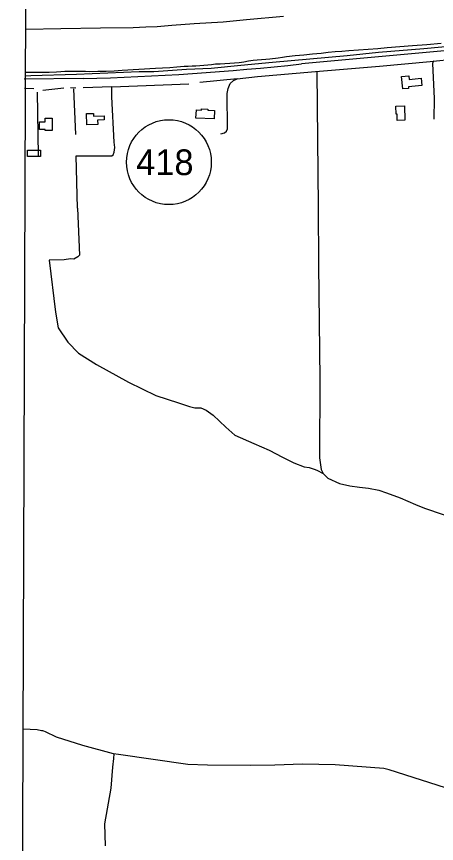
# Model space of a CAD drawing. Extents: x 3146026 to 3183936, y 897894 to 923344.
# Drawn here: x 3150246 to 3151879, y 910091 to 913306 of the extents above; entities that cross this region are included whole.
import ezdxf

# ---------------------------------------------------------------- set-up
doc = ezdxf.new("R2010")
doc.units = 0
for name, color, linetype in [('V-BLDG-OTLN', 7, 'Continuous'), ('V-GRID-FRAM', 7, 'Continuous'), ('V-LEVE-TOET', 7, 'Continuous'), ('V-ROAD-CNTR', 7, 'Continuous'), ('V-ROAD-IDEN', 7, 'Continuous'), ('V-TOPO-SHOR', 7, 'Continuous')]:
    doc.layers.add(name, color=color, linetype=linetype)

msp = doc.modelspace()

# ---------------------------------------------------------------- linework, layer by layer
at = {"layer": 'V-BLDG-OTLN'}
for points in [[(3151819.8, 913066), (3151822.6, 913037.5), (3151770.6, 913032.5), (3151771.2, 913026.5), (3151748.2, 913024.2), (3151743.5, 913072.5), (3151772.3, 913075.2), (3151773.6, 913061.5)], [(3151014.2, 912907.6), (3150943.7, 912911.2), (3150945.3, 912943), (3150965.4, 912942), (3150965.6, 912947.3), (3150990.5, 912946), (3150990.2, 912941.7), (3151015.9, 912940.4)], [(3151754.5, 912958.9), (3151756.3, 912903.2), (3151726.6, 912902.2), (3151725.9, 912926.1), (3151722.9, 912926), (3151721.8, 912957.9)], [(3150384.9, 912911.2), (3150385, 912862.5), (3150357.3, 912862.4), (3150357.3, 912866.7), (3150335.4, 912866.7), (3150335.4, 912896.7), (3150357.4, 912896.7), (3150357.4, 912911.1)], [(3150586.7, 912919.8), (3150587.1, 912903.7), (3150561.4, 912903), (3150561.8, 912886.3), (3150519.5, 912885.2), (3150518.3, 912928.8), (3150544.6, 912929.4), (3150544.8, 912918.7)], [(3150339.3, 912786.6), (3150339.2, 912762.1), (3150288.7, 912762.3), (3150288.8, 912786.8)]]:
    msp.add_lwpolyline(points, close=True, dxfattribs=at)
at = {"layer": 'V-GRID-FRAM'}
msp.add_lwpolyline([(3150311.9, 921563.1), (3181637, 921462.9), (3181586.7, 903274.3), (3150245.8, 903374.5), (3150311.9, 921563.1)], dxfattribs=at)
at = {"layer": 'V-LEVE-TOET'}
for points in [[(3150281.7, 913256.7), (3150418.2, 913258.6), (3150572.4, 913261.4), (3150699.2, 913263.7), (3150748.3, 913265.1), (3150792.4, 913266.8), (3150850.4, 913271.8), (3150936.8, 913278.2), (3151049.1, 913284.7), (3151140.2, 913293.8), (3151284.7, 913307.1)], [(3151897.2, 913200.9), (3151841.5, 913196.2), (3151785.8, 913192), (3151737, 913188.1), (3151688.2, 913184.1), (3151650.9, 913180.7), (3151613.4, 913177.5), (3151576, 913174.5), (3151538.6, 913171.8), (3151511.6, 913170.1), (3151484.8, 913168), (3151457.9, 913165.5), (3151431.1, 913162.6), (3151397.3, 913159.3), (3151363.6, 913156), (3151329.8, 913152.6), (3151296.1, 913149), (3151279.9, 913146.6), (3151263.7, 913144.4), (3151231.3, 913140.6), (3151215, 913139), (3151198.7, 913137.6), (3151182.4, 913136.4), (3151166.1, 913135.4), (3151148, 913131.9), (3151129.9, 913128.9), (3151111.7, 913126.4), (3151093.4, 913124.3), (3151075.1, 913122.6), (3151056.7, 913121.4), (3151038.4, 913120.6), (3151020, 913120.3), (3151004.8, 913118.2), (3150989.6, 913116.5), (3150974.4, 913115), (3150959.1, 913113.8), (3150943.8, 913112.8), (3150928.5, 913112.2), (3150913.2, 913111.8), (3150897.9, 913111.7), (3150869.9, 913108.7), (3150841.9, 913106.4), (3150813.9, 913104.7), (3150785.8, 913103.6), (3150721.6, 913099.9), (3150657.3, 913096.1), (3150625.7, 913094), (3150594, 913092.5), (3150562.3, 913091.7), (3150530.5, 913091.4), (3150514.4, 913091.9), (3150498.3, 913092.3)], [(3150498.3, 913092.3), (3150482.2, 913092.4), (3150466, 913092.3), (3150449.9, 913092), (3150433.8, 913091.5), (3150417.6, 913090.8), (3150401.5, 913089.8), (3150373.1, 913088.7), (3150344.6, 913088), (3150316.1, 913087.6), (3150287.6, 913087.7), (3150281.1, 913087.8)]]:
    msp.add_lwpolyline(points, dxfattribs=at)
at = {"layer": 'V-ROAD-CNTR'}
for points in [[(3152764.7, 913249.6), (3151354, 913121.3)], [(3150504.4, 913064.4), (3150275, 913062.2)]]:
    msp.add_lwpolyline(points, dxfattribs=at)
msp.add_arc((3150227.2, 923566.8), 10506.1, 271.51204, 276.15701, dxfattribs=at)
at = {"layer": 'V-ROAD-IDEN'}
msp.add_circle((3150838.5, 912739.6), 165, dxfattribs=at)
at = {"layer": 'V-TOPO-SHOR'}
for p, q in [((3151854.8, 913131.3), (3152006.9, 913146.9)), ((3150616.2, 913032.5), (3150916.2, 913044.2)), ((3151104.7, 913063.2), (3150958.4, 913048.9)), ((3150313.3, 913025.3), (3150277.1, 913026.2)), ((3150326, 913011.9), (3150329.7, 912765)), ((3150348, 913020), (3150429.5, 913028)), ((3150456.4, 913029.5), (3150476, 913028.2)), ((3150467.9, 913024.8), (3150475.6, 912846.8))]:
    msp.add_line(p, q, dxfattribs=at)
for points in [[(3153574.1, 913209.4), (3153385.3, 913235.5), (3153165.9, 913253.6), (3153079.7, 913260.9), (3152956.4, 913265.6), (3152855.6, 913267.5), (3152817.2, 913269.3), (3152700.8, 913259.3), (3152400.2, 913227.3), (3152126, 913206.2), (3152036.5, 913196.2), (3151984.9, 913193.9), (3151829.9, 913179.9), (3151653.9, 913165.6), (3151531.6, 913152.9), (3151242.1, 913127.1), (3151118.4, 913115.8), (3151003.4, 913104.3), (3150906.8, 913100.4), (3150779.6, 913091.4), (3150722.9, 913091.4), (3150478.8, 913080.4), (3150300.9, 913075.7), (3150277.6, 913073.4)], [(3151408.8, 913091.5), (3151657.6, 913112.5), (3151854.8, 913131.3)], [(3151867.2, 913133.2), (3151864, 913123.1), (3151870.6, 912986.5), (3151869.2, 912907.4)], [(3151040.3, 912849.4), (3151054.9, 912853.3), (3151062.3, 912860.4), (3151066.2, 912869.7), (3151065.5, 913006.2), (3151068.9, 913026.4), (3151076.6, 913045.1), (3151089.3, 913057.1), (3151104.7, 913063.2), (3151182.6, 913072.1), (3151408.8, 913091.5)], [(3151414.6, 913091.4), (3151419.7, 912567.2), (3151421, 912339.3), (3151425.3, 911896.4), (3151424.5, 911590.2), (3151430.5, 911545), (3151438.1, 911529.6), (3151456.5, 911511.7), (3151502.4, 911490.1), (3151542.8, 911481.8), (3151580.4, 911476.5), (3151615.2, 911472.6), (3151654.9, 911465.1), (3151685.1, 911454.1), (3151738.3, 911435.3), (3151797.8, 911408.3), (3151833, 911395.1), (3151977.6, 911345.5), (3152095.1, 911315.6), (3152179.6, 911298.1), (3152225, 911287.5), (3152260.5, 911282.9), (3152300.4, 911284), (3152313.5, 911283.7)], [(3150483.3, 912561.4), (3150477.7, 912764), (3150616.4, 912764), (3150622.3, 912768.2), (3150626.2, 912779), (3150628.8, 912797), (3150625, 912817.5), (3150615.9, 912994.1), (3150616.2, 913032.5), (3150505, 913028.9)], [(3150483.3, 912561.4), (3150490.8, 912377.5), (3150484.8, 912371.9), (3150468.6, 912362.1), (3150455.6, 912363.9), (3150430.8, 912360.2), (3150372.7, 912358.9), (3150397.9, 912156.4), (3150407.9, 912095.2), (3150445.6, 912040.5), (3150486.6, 911997.3), (3150556.6, 911953.4), (3150681, 911884.8), (3150787.1, 911832.7), (3150876.3, 911804.2), (3150918.1, 911790), (3150939.7, 911785.1), (3150962.9, 911784.5), (3150983, 911775.2), (3151010.1, 911755.7), (3151059.6, 911709.4), (3151095.1, 911677.9), (3151168.3, 911645.5), (3151228.6, 911620.7), (3151280.1, 911593.2), (3151324.5, 911570.3), (3151364.8, 911554.7), (3151383.6, 911552.8), (3151403.7, 911546.4), (3151413.8, 911541.8), (3151438.1, 911529.6)], [(3152496.7, 910100.6), (3152308.5, 910167.6), (3152106.8, 910240.1), (3151946.4, 910296.6), (3151695, 910377.9), (3151675.1, 910382.7), (3151484.7, 910396.4), (3151358.1, 910399.1), (3151250.4, 910395.3), (3151155, 910394.4), (3150989.3, 910395.4), (3150911.6, 910398.3), (3150642.3, 910436.7), (3150622.4, 910439.3), (3150504, 910472.5), (3150401.3, 910504.2), (3150358.7, 910524.8), (3150352.5, 910527.2), (3150347.6, 910528.9), (3150343.5, 910529.5), (3150325.9, 910532.9), (3150271.8, 910535.5)], [(3150592.5, 910081.4), (3150588.7, 910167), (3150614, 910306), (3150621, 910387.6), (3150624.3, 910421.3), (3150626, 910439.3)]]:
    msp.add_lwpolyline(points, dxfattribs=at)

# ---------------------------------------------------------------- texts
at = {"layer": 'V-ROAD-IDEN'}
msp.add_text('418', height=100, rotation=359.666, dxfattribs=at).set_placement((3150711, 912690.3))

doc.saveas('drawing.dxf')
